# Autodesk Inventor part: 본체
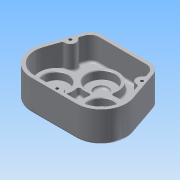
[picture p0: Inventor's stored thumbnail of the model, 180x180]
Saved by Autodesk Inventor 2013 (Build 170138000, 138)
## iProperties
Created: 2014-12
Part Number: 본체
Material: 알루미늄 6061
Document SubType Name: Modeling
Designer: Administrator
Density: 2.71 g/cm^3
Mass: 613.435 g
Surface Area: 665.181 cm^2
Volume: 226.36 cm^3
Author: Administrator
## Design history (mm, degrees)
sketch "스케치1"
  geometry: L1 (0, 0)-(-32.527, -32.527); L2 (0, 0)-(32.527, -32.527); L3 (0, 0)-(0, -46); L4 (-47, 36)-(47, 36); L5 (-32.527, -68.527)-(32.527, -68.527); L6 (-66.565, -20.803)-(-47, 36); L7 (66.565, -20.803)-(47, 36); A1 r 46 centre (0, 0) between (-32.527, -32.527) and (0, -46); A2 r 36 centre (32.527, -32.527) between (32.527, -68.527) and (66.565, -20.803); A3 r 36 centre (32.527, -32.527) between (-0.86, -45.992) and (0, -47.954); A4 r 36 centre (-32.527, -32.527) between (0, -47.954) and (0.86, -45.992); A5 r 36 centre (-32.527, -32.527) between (-66.565, -20.803) and (-32.527, -68.527); 3 further points
  constraints: 14 end point, 13 point on circle, 5 centre point, 3 coincident, 2 midpoint, 2 tangent, 2 vertical alignment, 1 parallel, 1 perpendicular, 1 vertical
  dimensions: "d2" = 92 diameter of A1; "d3" = 45 deg angle of L3 L1; "d5" = 45 deg angle of L2 L3; "d9" = 36 distance from line of L4 point (0, 0); "d10" = 94 distance of L4.start L4.end; "d11" = 36 distance from line of L1.end L5; "d12" = 36 radius of A5; "d13" = 36 radius of A2
extrude "돌출1" new body sketch "스케치1" distance "d14" = 44; taper "d15" = 0 deg
fillet "모깎기1" dims "d16" = 18
sketch "스케치2"
  geometry: L1 (46.453, 22.233)-(61.837, -22.432) reference; L2 (32.527, -63.527)-(-32.527, -63.527) reference; L3 (-61.837, -22.432)-(-46.453, 22.233) reference; L4 (34.162, 36)-(-34.162, 36) reference; L5 (-51.181, 23.862)-(-66.565, -20.803) reference; L6 (-32.527, -68.527)-(32.527, -68.527) reference; L7 (66.565, -20.803)-(51.181, 23.862) reference; L8 (-49.095, 14.564)-(-53.822, 16.192); L9 (-54.305, -0.564)-(-59.033, 1.064); L10 (49.095, 14.564)-(53.822, 16.192); L11 (54.305, -0.564)-(59.033, 1.064); L12 (-8, -63.527)-(-8, -68.527); L13 (8, -63.527)-(8, -68.527); A1 r 8 centre (-51.7, 7) between (-54.305, -0.564) and (-49.095, 14.564); A2 r 8 centre (51.7, 7) between (49.095, 14.564) and (54.305, -0.564); A3 r 8 centre (0, -63.527) between (8, -63.527) and (-8, -63.527); 1 further point
  constraints: 12 end point, 11 point on line, 6 point on circle, 6 tangent, 5 perpendicular, 3 centre point, 1 midpoint, 1 parallel
  dimensions: "d18" = 16 diameter of A1; "d19" = 16 diameter of A2; "d20" = 16 diameter of A3; "d21" = 29 distance from line of L4 A1.centre; "d22" = 29 distance from line of L4 A2.centre
extrude "돌출2" join sketch "스케치2" stored distance "d23" = 0; taper "d24" = 0 deg
extrude "돌출3" join sketch "스케치2" stored distance "d25" = 0; taper "d26" = 0 deg
sketch "스케치6"
  geometry: C1 r 20 at (-32.527, -32.527); C2 r 20 at (32.527, -32.527); A1 r 36 centre (32.527, -32.527) between (32.527, -68.527) and (66.565, -20.803) reference; A2 r 36 centre (-32.527, -32.527) between (-66.565, -20.803) and (-32.527, -68.527) reference; 1 further point
  constraints: 2 centre point, 2 coincident
  dimensions: "d41" = 40 diameter of C1; "d42" = 40 diameter of C2
extrude "돌출7" join sketch "스케치6" distance "d43" = 7; taper "d44" = -10 deg
sketch "스케치7"
  geometry: C1 r 18.766 at (0, 0) reference; C2 r 18.766 at (65.054, 0) reference; C3 r 15 at (0, 0); C4 r 15 at (65.054, 0); 1 further point
  constraints: 2 centre point, 2 coincident
  dimensions: "d45" = 30 diameter of C3; "d46" = 30 diameter of C4
extrude "돌출8" cut sketch "스케치7" distance "d47" = 7; taper "d48" = 0 deg
sketch "스케치8"
  geometry: L1 (-1.635, 68.527)-(66.689, 68.527) reference; L2 (83.708, 56.389)-(99.091, 11.723) reference; L3 (65.054, -36)-(0, -36) reference; L4 (-34.038, 11.723)-(-18.654, 56.389) reference; C1 r 15 at (0, 0) reference; C2 r 15 at (65.054, 0) reference; C3 r 20 at (0, 0) reference; C4 r 20 at (65.054, 0) reference; C5 r 7.75 at (0, 0); C6 r 7.75 at (65.054, 0); A1 r 18 centre (-1.635, 50.527) between (-1.635, 68.527) and (-18.654, 56.389) reference; A2 r 18 centre (66.689, 50.527) between (83.708, 56.389) and (66.689, 68.527) reference; A3 r 36 centre (65.054, 0) between (65.054, -36) and (99.091, 11.723) reference; A4 r 36 centre (0, 0) between (-34.038, 11.723) and (0, -36) reference; 1 further point
  constraints: 2 centre point, 2 coincident
  dimensions: "d49" = 15.5 diameter of C5; "d50" = 15.5 diameter of C6
extrude "돌출9" cut sketch "스케치8" stored distance "d51" = 7; taper "d52" = 0 deg
fillet "모깎기3" dims "d81" = 3
fillet "모깎기4" dims "d82" = 3
fillet "모깎기6" dims "d87" = 0.1
sketch "스케치9"
  geometry: L1 (34.162, 36)-(-34.162, 36) reference; 2 further points
  constraints: 1 vertical alignment, 1 other
  dimensions: "d88" = 30 distance from line of L1 point (0, 6)
feature "엠보싱1" sketch "스케치9" dims "d2" = 92, "d89" = 1, "d90" = 0
chamfer "모따기3" distance "d94" = 1; stored, may be unused: second distance "d95" = 2, angle "d96" = 45 deg
sketch "스케치10"
  geometry: L1 (-32.527, -68.527)-(32.527, -68.527) reference; L2 (34.162, 36)-(-34.162, 36) reference; L3 (-34.162, 31)-(34.162, 31); L4 (-32.527, -63.527)-(32.527, -63.527); L5 (-46.453, 22.233)-(-61.837, -22.432); L6 (46.453, 22.233)-(61.837, -22.432); C1 r 7.75 at (32.527, -32.527) reference; C2 r 7.75 at (-32.527, -32.527) reference; A1 r 36 centre (32.527, -32.527) between (32.527, -68.527) and (66.565, -20.803) reference; A2 r 18 centre (34.162, 18) between (51.181, 23.862) and (34.162, 36) reference; A3 r 18 centre (-34.162, 18) between (-34.162, 36) and (-51.181, 23.862) reference; A4 r 36 centre (-32.527, -32.527) between (-66.565, -20.803) and (-32.527, -68.527) reference; A5 r 31 centre (-32.527, -32.527) between (-61.837, -22.432) and (-32.527, -63.527); A6 r 31 centre (32.527, -32.527) between (32.527, -63.527) and (61.837, -22.432); A7 r 13 centre (-34.162, 18) between (-34.162, 31) and (-46.453, 22.233); A8 r 13 centre (34.162, 18) between (46.453, 22.233) and (34.162, 31); 1 further point
  constraints: 8 end point, 8 point on circle, 4 centre point, 4 coincident, 4 tangent, 2 parallel
  dimensions: "d98" = 5 distance between parallel lines of L2 L3; "d99" = 5 radial gap between concentric circles of A3 A7; "d100" = 5 radial gap between concentric circles of A2 A8; "d101" = 5 radial gap between concentric circles of A4 A5; "d102" = 5 radial gap between concentric circles of A1 A6; "d103" = 5 distance between parallel lines of L1 L4
extrude "돌출10" cut sketch "스케치10" distance "d104" = 34; taper "d105" = 0 deg
sketch "스케치11"
  geometry: C1 r 7.75 at (-32.527, -32.527) reference; C2 r 7.75 at (32.527, -32.527) reference; A1 r 31 centre (-32.527, -32.527) between (-61.837, -22.432) and (-32.527, -63.527) reference; A2 r 31 centre (32.527, -32.527) between (32.527, -63.527) and (61.837, -22.432) reference; A3 r 24 centre (-32.527, -32.527) between (-21.111, -11.416) and (-11.416, -21.111); A4 r 24 centre (32.527, -32.527) between (11.416, -21.111) and (21.111, -11.416); A5 r 24 centre (0, 0) between (-11.416, -21.111) and (11.416, -21.111); A6 r 24 centre (0, 0) between (21.111, -11.416) and (-21.111, -11.416); 1 further point
  constraints: 8 point on circle, 4 centre point, 3 coincident, 1 concentric
  dimensions: "d107" = 48 diameter of A3; "d108" = 48 diameter of A4; "d109" = 24 radius of A6
extrude "돌출11" join sketch "스케치11" distance "d110" = 11; taper "d111" = 0 deg
sketch "스케치12"
  geometry: C1 r 20 at (0, 0); C2 r 17.5 at (-32.527, -32.527); C3 r 17.5 at (32.527, -32.527); A1 r 24 centre (-32.527, -32.527) between (-21.111, -11.416) and (-11.416, -21.111) reference; A2 r 24 centre (32.527, -32.527) between (11.416, -21.111) and (21.111, -11.416) reference; A3 r 24 centre (0, 0) between (21.111, -11.416) and (-21.111, -11.416) reference
  constraints: 3 centre point, 3 coincident
  dimensions: "d112" = 40 diameter of C1; "d113" = 35 diameter of C2; "d114" = 35 diameter of C3
extrude "돌출12" cut sketch "스케치12" distance "d115" = 11; taper "d116" = 0 deg
sketch "스케치13"
  geometry: C1 r 20 at (0, 0) reference; C2 r 10 at (0, 0)
  constraints: 1 centre point, 1 coincident
  dimensions: "d117" = 20 diameter of C2
extrude "돌출13" cut sketch "스케치13" distance "d118" = 3; taper "d119" = 0 deg
sketch "스케치14"
  geometry: L1 (32.527, -63.527)-(-32.527, -63.527) reference; L2 (-61.837, -22.432)-(-46.453, 22.233) reference; L3 (-32.527, -68.527)-(32.527, -68.527) reference; L4 (34.162, 36)-(-34.162, 36) reference; L5 (-51.181, 23.862)-(-66.565, -20.803) reference; L6 (-8, -63.527)-(-8, -68.527); L7 (8, -63.527)-(8, -68.527); L8 (-49.095, 14.564)-(-53.822, 16.192); L9 (-54.305, -0.564)-(-59.033, 1.064); A1 r 8 centre (-51.7, 7) between (-54.305, -0.564) and (-49.095, 14.564); A2 r 8 centre (0, -63.527) between (8, -63.527) and (-8, -63.527); 1 further point
  constraints: 8 end point, 5 point on line, 4 point on circle, 4 tangent, 2 centre point, 2 parallel, 2 perpendicular, 1 midpoint
  dimensions: "d120" = 16 diameter of A1; "d122" = 16 diameter of A2; "d123" = 29 distance from line of L4 A1.centre
extrude "돌출14" join sketch "스케치14" stored distance "d124" = 0; taper "d125" = 0 deg
extrude "돌출15" join sketch "스케치14" stored distance "d126" = 0; taper "d127" = 0 deg
hole "구멍4" diameter "d130" = 4.134; stored, may be unused: countersink angle "d134" = 90 deg, drill point angle "d136" = 118 deg; dims "d128" = 10, "d129" = 10, "d131" = 20, "d132" = 4, "d133" = 2, "d135" = 23
hole "구멍5" diameter "d139" = 4.134; stored, may be unused: countersink angle "d143" = 90 deg, drill point angle "d145" = 118 deg; dims "d137" = 10, "d138" = 10, "d140" = 20, "d141" = 4, "d142" = 2, "d144" = 23
fillet "모깎기7" dims "d146" = 3
fillet "모깎기8" dims "d147" = 3
chamfer "모따기4" distance "d148" = 1; stored, may be unused: second distance "d149" = 2, angle "d150" = 45 deg
fillet "모깎기9" dims "d151" = 0.3
sketch "스케치15"
  geometry: C1 r 20 at (0, 0) reference; C2 r 20 at (0, 0)
  constraints: 1 centre point, 1 coincident
  dimensions: "d153" = 40 diameter of C2
extrude "돌출16" cut sketch "스케치15" distance "d154" = 1; taper "d155" = 0 deg
fillet "모깎기11" dims "d156" = 0.3
sketch "스케치16"
  geometry: C1 r 10 at (0, 0) reference; C2 r 10 at (0, 0)
  constraints: 1 centre point, 1 coincident
  dimensions: "d157" = 20 diameter of C2
extrude "돌출17" join sketch "스케치16" stored distance "d158" = 1; taper "d159" = 0 deg
sketch "스케치17"
  geometry: C1 r 19.7 at (0, 0) reference; C2 r 10 at (0, 0)
  constraints: 1 centre point, 1 coincident
  dimensions: "d160" = 20 diameter of C2
extrude "돌출18" cut sketch "스케치17" distance "d161" = 3; taper "d162" = 0 deg
fillet "모깎기12" dims "d163" = 3
node "솔리드1"
mirror "대칭1"
mirror "대칭2"
node "절단 모서리 투영1"
node "절단 모서리 투영2"
other parameters: "d7" = 72, "d8" = 72, "d27" = 48, "d106" = 48
